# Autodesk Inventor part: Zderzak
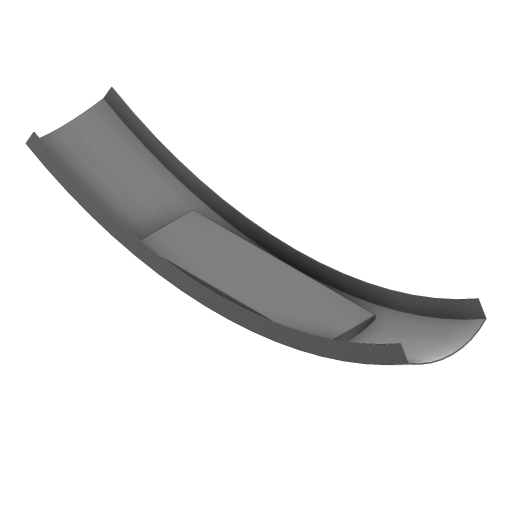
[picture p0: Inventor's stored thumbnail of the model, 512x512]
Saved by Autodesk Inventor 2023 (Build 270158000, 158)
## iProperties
Created: 2021-01
Part Number: Zderzak
Material: Tworzywo o ultrawysokiej masie cząsteczkowej, czarne
Document SubType Name: Modeling
Designer: Home
Density: 0.94 g/cm^3
Appearance: Gładki — czarny
Mass: 403.115 g
Surface Area: 4335.41 cm^2
Volume: 428.846 cm^3
Author: Home
## Parameters: d6 = 0, d7 = 0, d12 = 0, d13 = 5 mm, d14 = 0, d15 = 5 mm, d16 = 0, d17 = 2 mm
